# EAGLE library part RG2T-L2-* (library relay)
HIGH FREQUENCY RELAYS WITH 1C AND 2C CONTACTS NAiS Source: http://www.mew-europe.com/.. en_ds_61302_0000.pdf
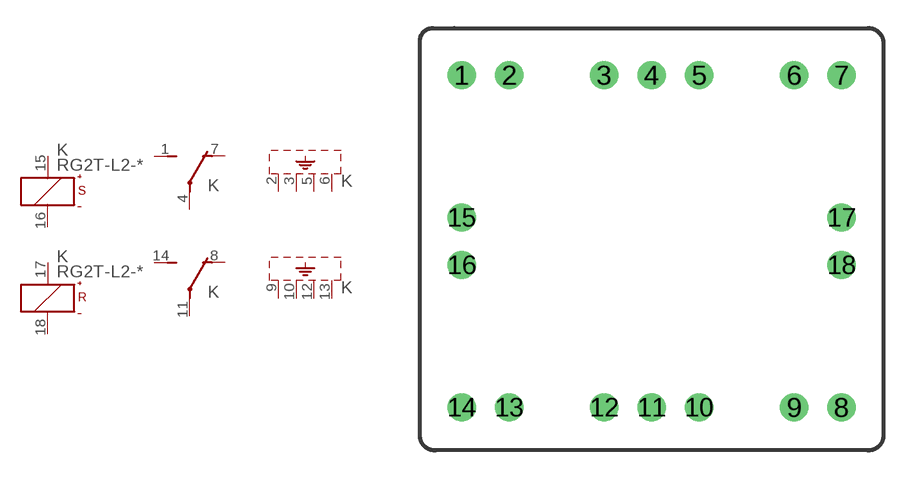
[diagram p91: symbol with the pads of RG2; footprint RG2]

Designator prefix K; gates S=K+-S R=K+-R 1=U 2=U S1=SHIELD-4 S2=SHIELD-4

## RG2T-L2-3V (OC_FARNELL: unknown; OC_NEWARK: unknown), RG2T-L2-5V (OC_FARNELL: unknown; OC_NEWARK: unknown), RG2T-L2-6V (OC_FARNELL: unknown; OC_NEWARK: unknown), RG2T-L2-9V (OC_FARNELL: unknown; OC_NEWARK: unknown), RG2T-L2-12V (OC_FARNELL: unknown; OC_NEWARK: unknown), RG2T-L2-24V (OC_FARNELL: unknown; OC_NEWARK: unknown), RG2T-L2-48V (OC_FARNELL: unknown; OC_NEWARK: unknown)  [RG2]
1  1:S  pas
2  S1:SH  pas
3  S1:SH  pas
4  1:P  pas
5  S1:SH  pas
6  S1:SH  pas
7  1:O  pas
8  2:O  pas
9  S2:SH  pas
10  S2:SH  pas
11  2:P  pas
12  S2:SH  pas
13  S2:SH  pas
14  2:S  pas
15  S:+  pas
16  S:-  pas
17  R:+  pas
18  R:-  pas

## Footprint RG2 (pad centres in mm)
HIGH FREQUENCY RELAYS WITH 1C AND 2C CONTACTS NAiS Source: http://www.mew-europe.com/.. en_ds_61302_0000.pdf
drill 1 round: 1 -10.16,8.89; 2 -7.62,8.89; 3 -2.54,8.89; 4 0,8.89; 5 2.54,8.89; 6 7.62,8.89; 7 10.16,8.89; 8 10.16,-8.89; 9 7.62,-8.89; 10 2.54,-8.89; 11 0,-8.89; 12 -2.54,-8.89; 13 -7.62,-8.89; 14 -10.16,-8.89; 15 -10.16,1.27; 16 -10.16,-1.27; 17 10.16,1.27; 18 10.16,-1.27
